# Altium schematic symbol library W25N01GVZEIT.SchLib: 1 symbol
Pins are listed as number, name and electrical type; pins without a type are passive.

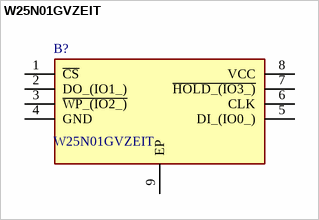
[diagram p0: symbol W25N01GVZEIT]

## W25N01GVZEIT
designator B?
1Gb QspiNAND Flash 104MHz SON8; Manufacturer_Name: Winbond; Geometry.Height: 0.8mm
footprint SON127P800X600X80-9N-D
pins: 1 ~{CS}, 2 DO_(IO1_), 3 ~{WP_(IO2_)}, 4 GND, 5 DI_(IO0_), 6 CLK, 7 ~{HOLD_(IO3_)}, 8 VCC, 9 EP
